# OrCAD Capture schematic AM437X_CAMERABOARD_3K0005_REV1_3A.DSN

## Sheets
1 Pg02: Camera: size C; title: AM437x Camera Board; rev: 1.3A; company: Texas Instruments; note: am437x_cameraboard_3k0005_rev1_3a.dsn; note: ARM MPU BU; note: Final
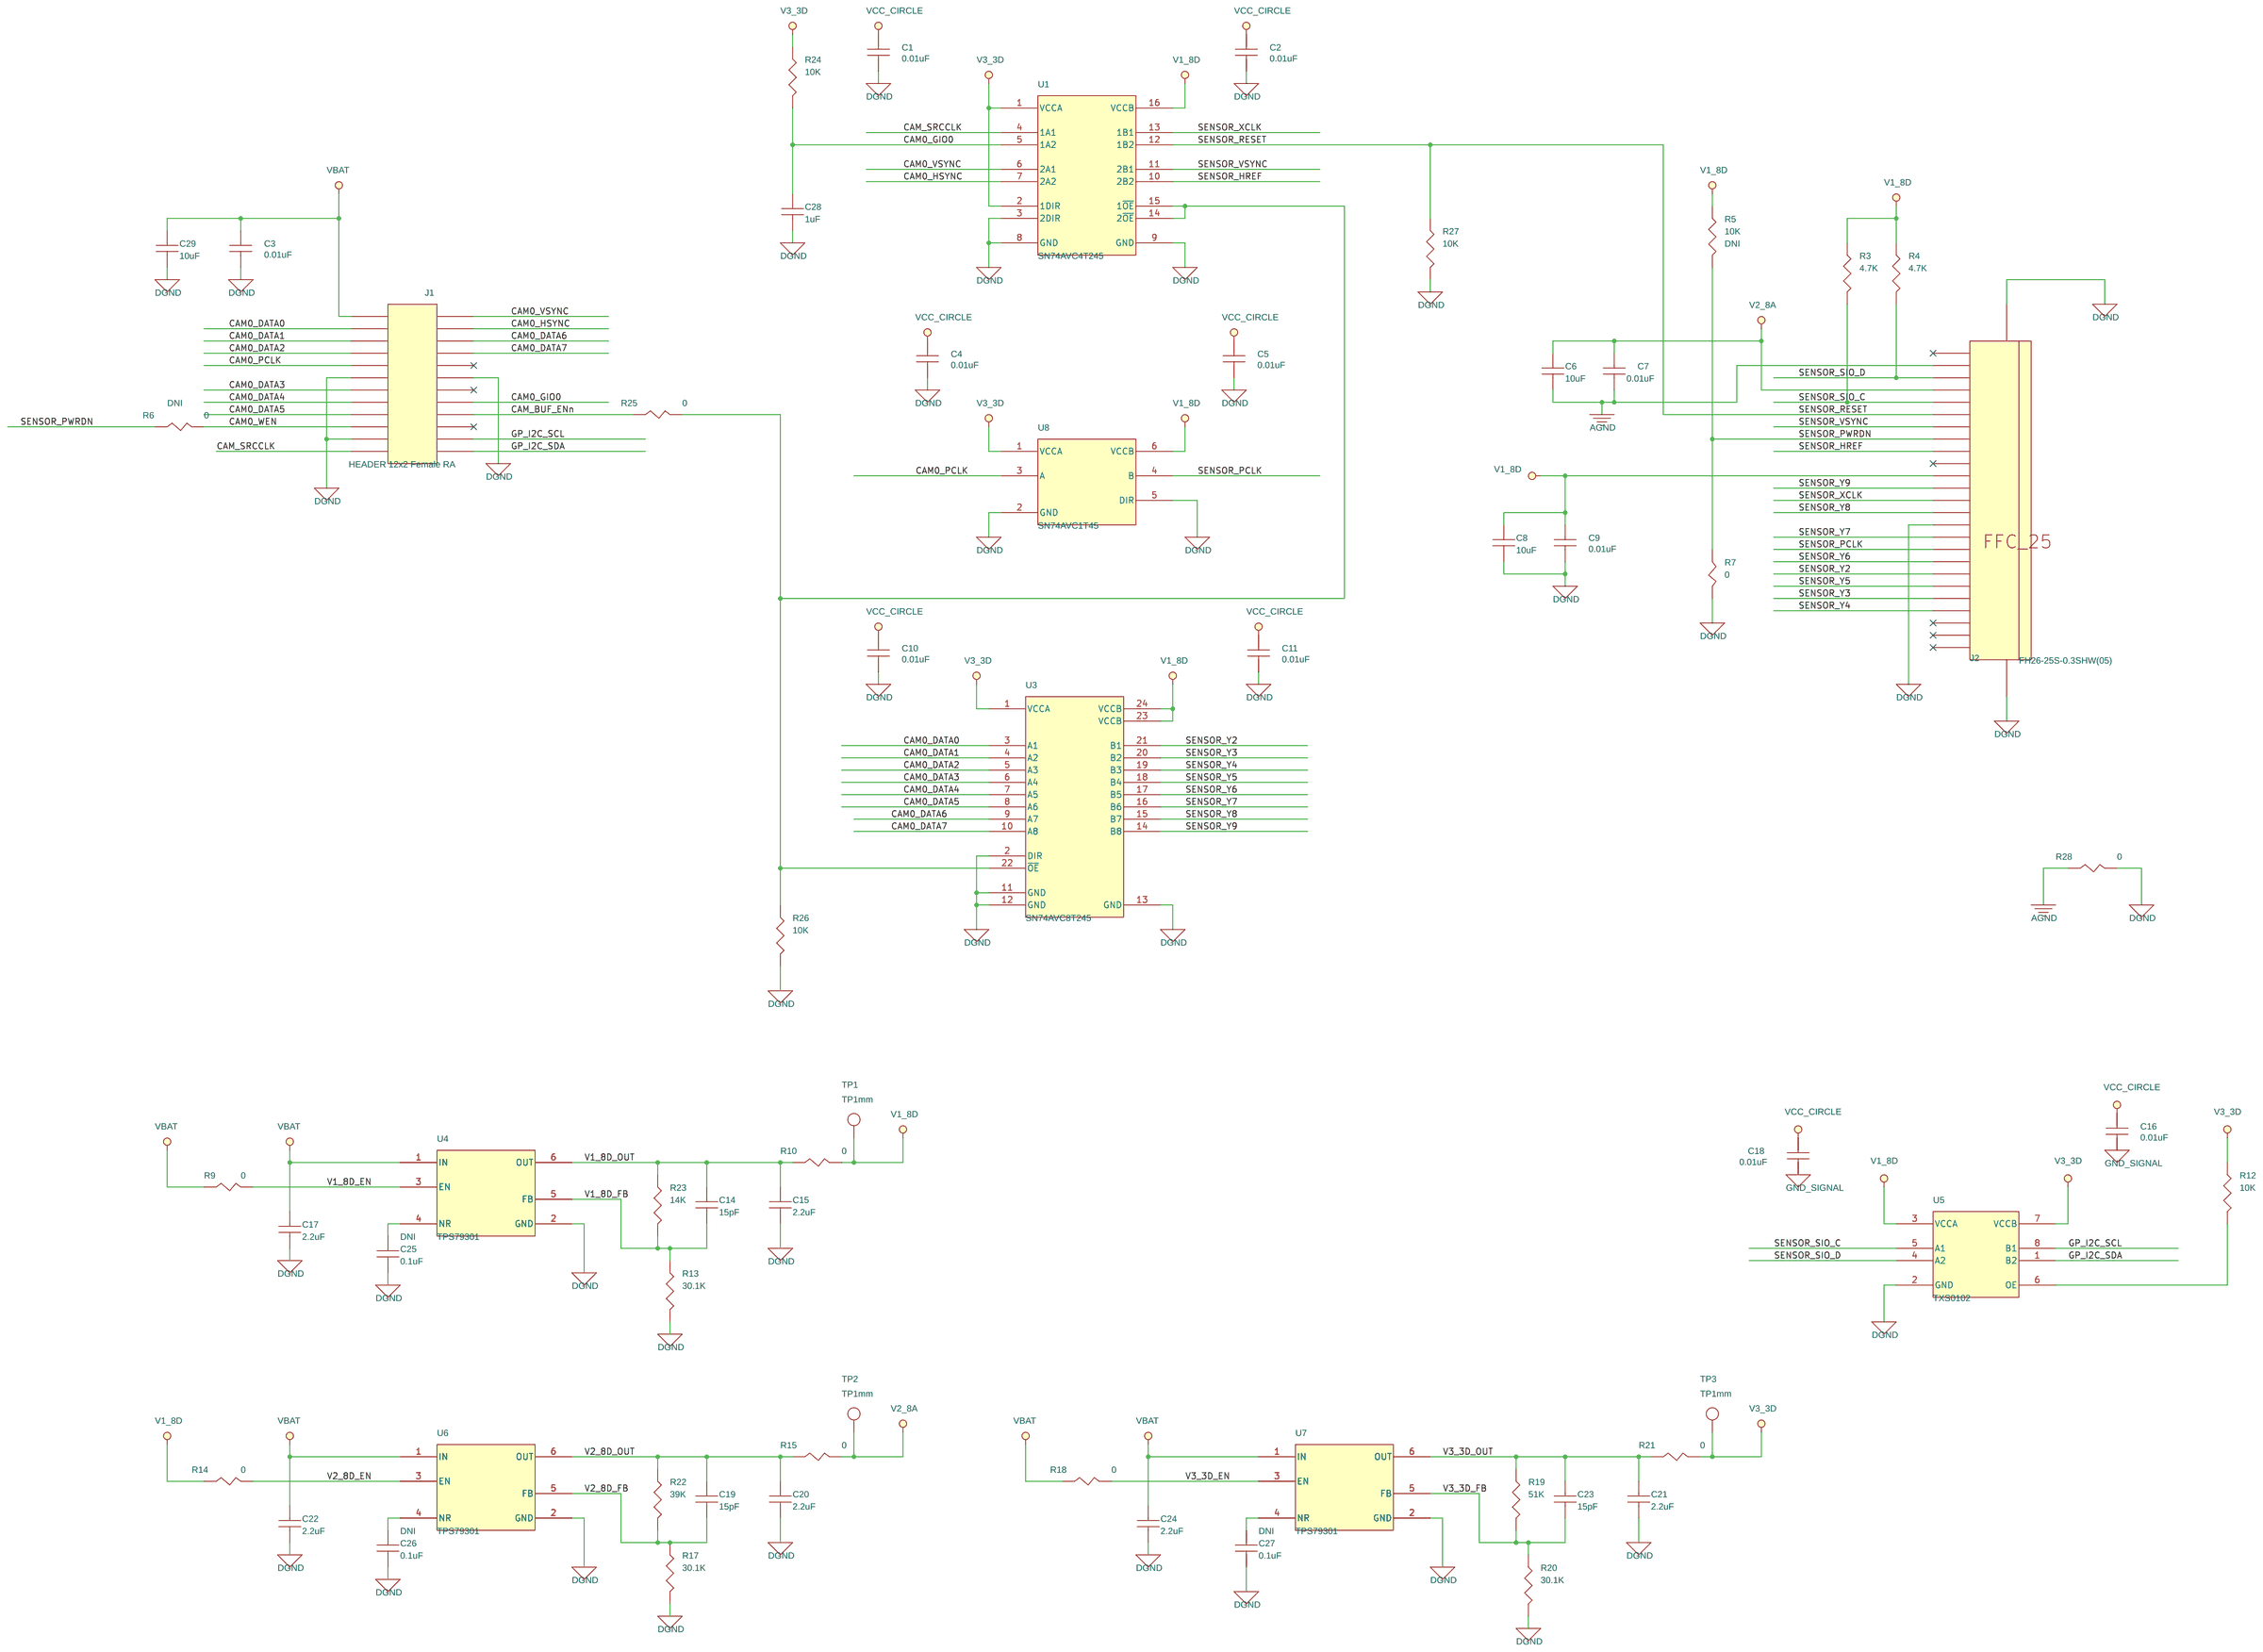
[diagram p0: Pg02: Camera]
2 Pg01: Title
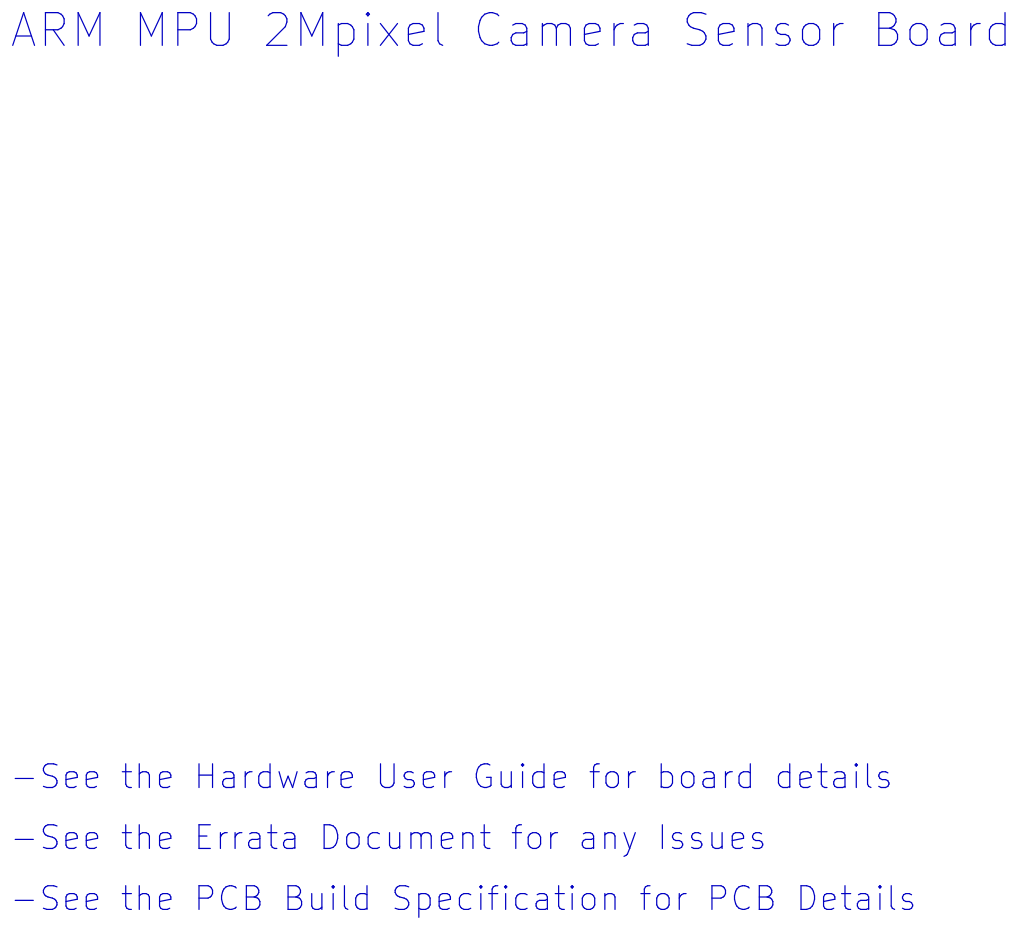
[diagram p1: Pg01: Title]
3 Pg03: Hardware Schematics
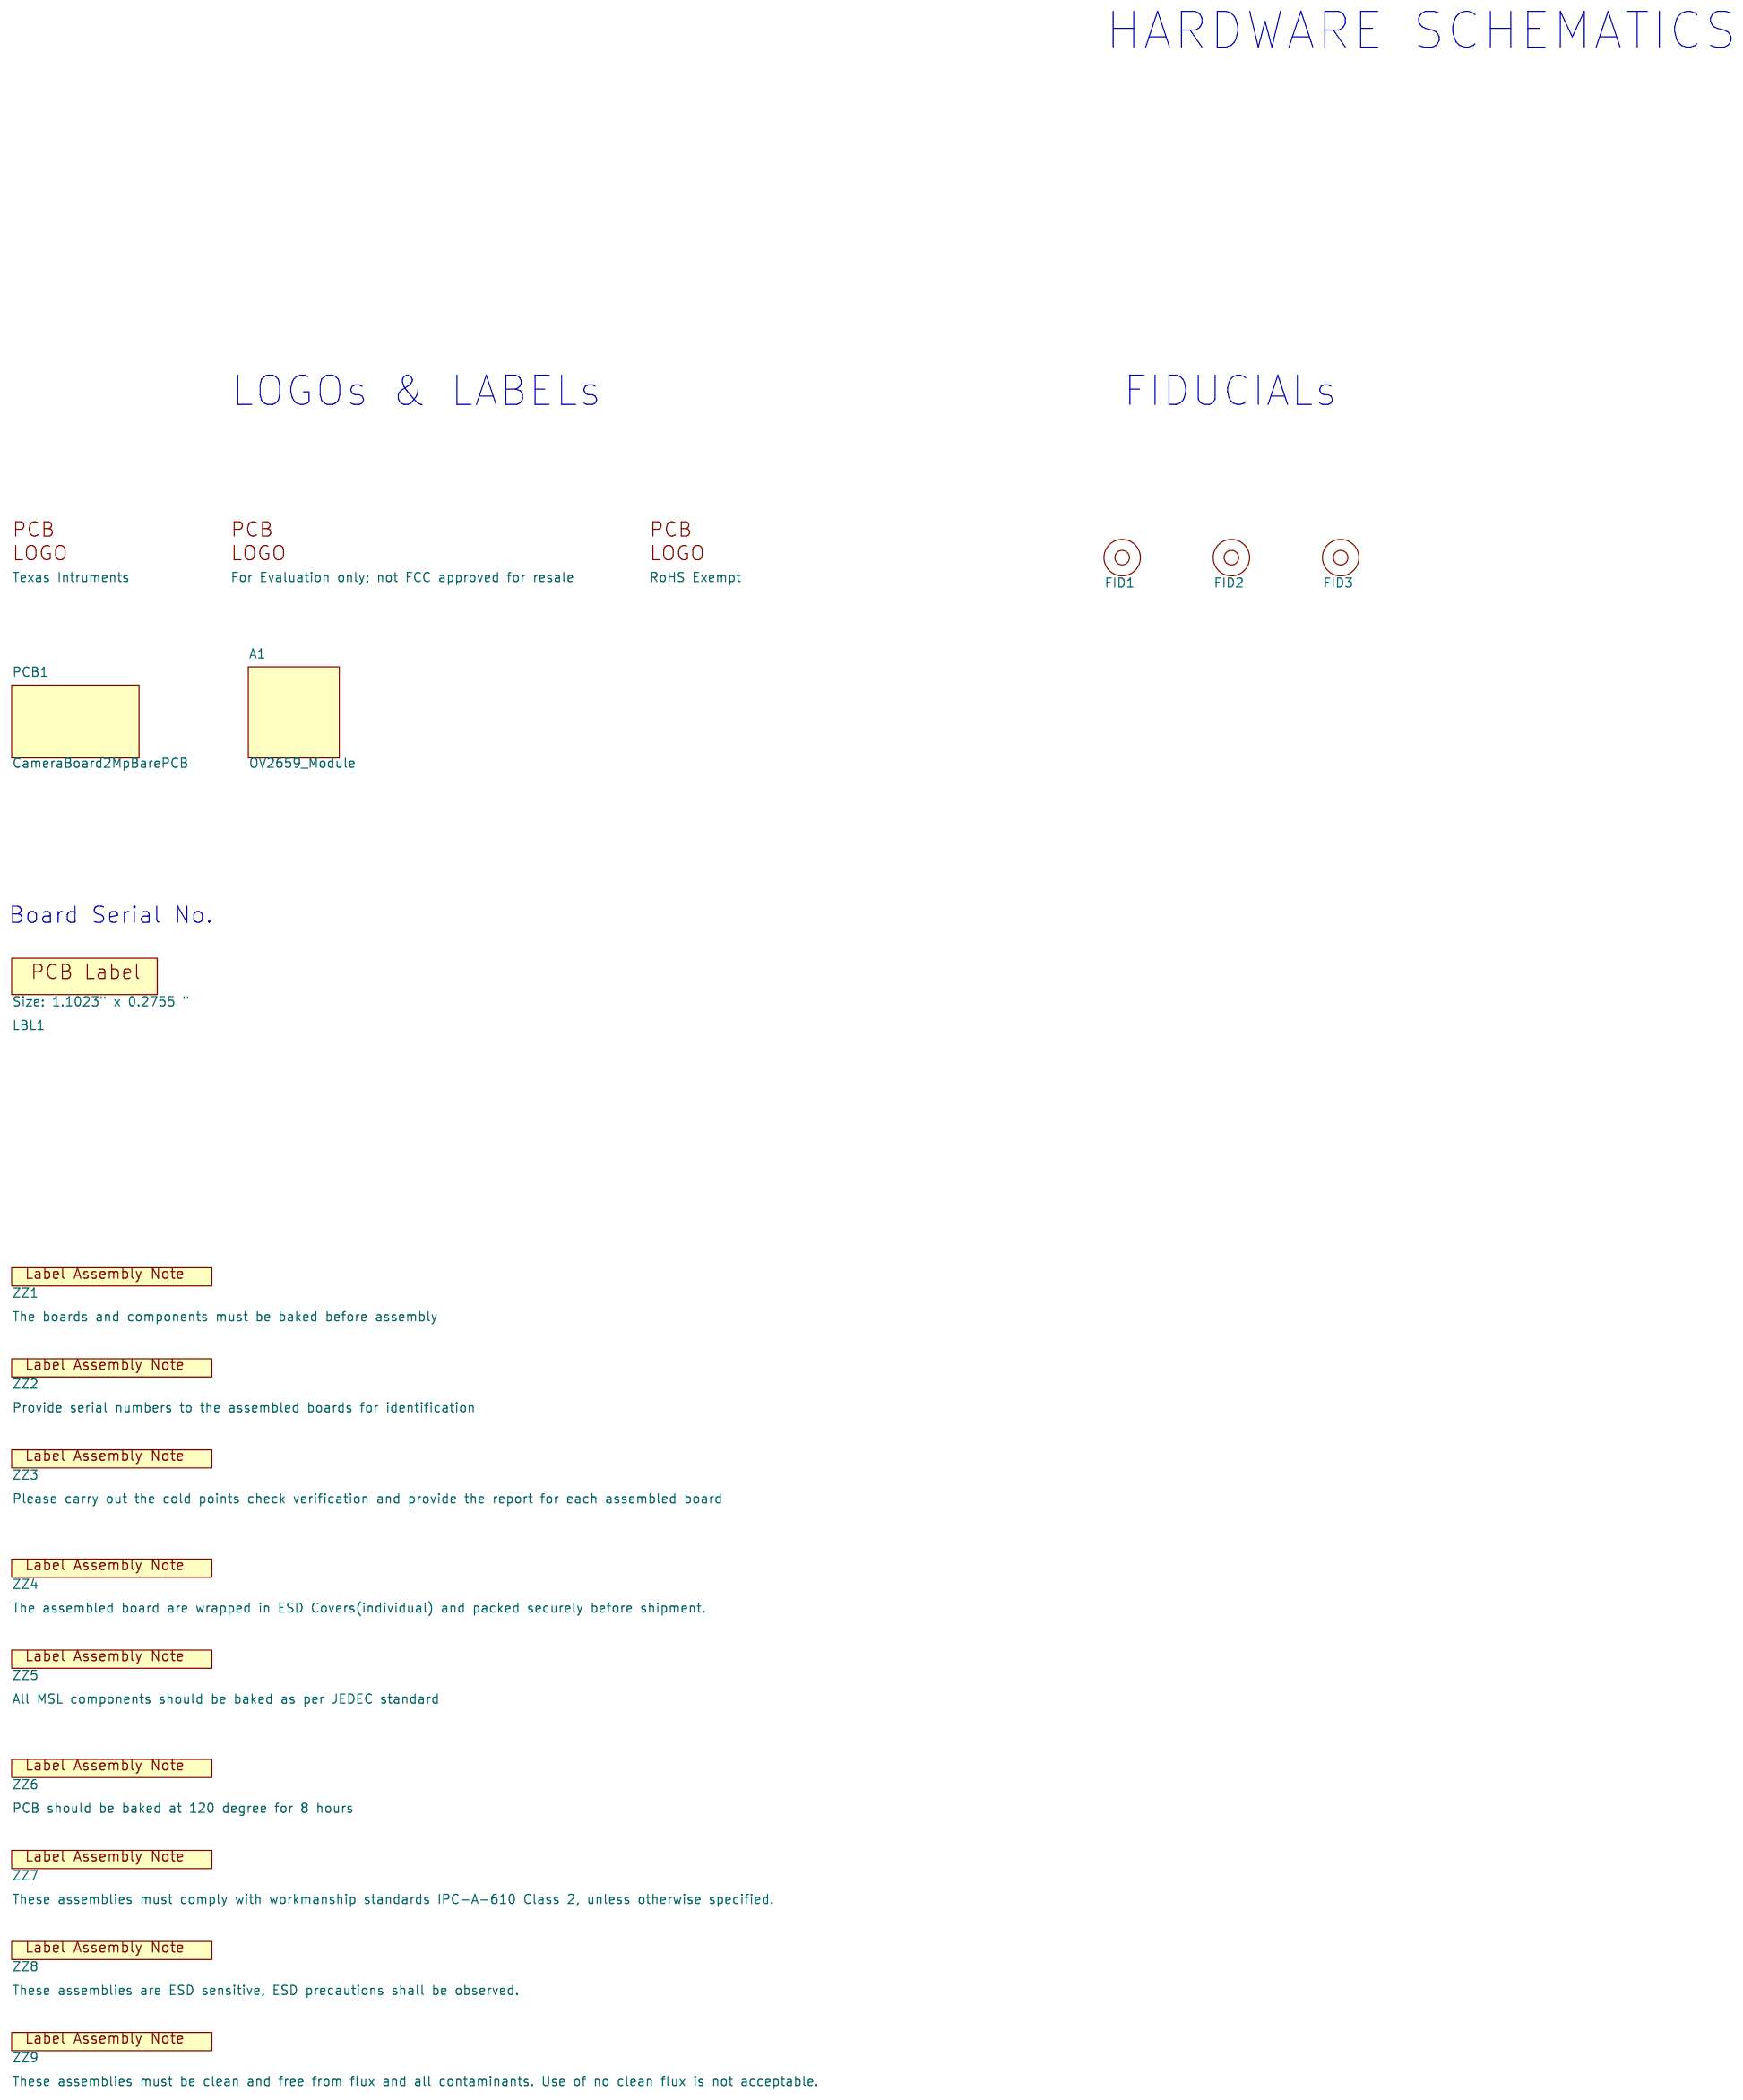
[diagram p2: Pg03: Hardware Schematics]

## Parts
sheet Pg02: Camera
C1  0.01uF  [SM-7351-CAP-0402]
C2  0.01uF  [SM-7351-CAP-0402]
C3  0.01uF  [SM-7351-CAP-0402]
C4  0.01uF  [SM-7351-CAP-0402]
C5  0.01uF  [SM-7351-CAP-0402]
C6  10uF  [SM-7351-CAP-0805]
C7  0.01uF  [SM-7351-CAP-0402]
C8  10uF  [SM-7351-CAP-0805]
C9  0.01uF  [SM-7351-CAP-0402]
C10  0.01uF  [SM-7351-CAP-0402]
C11  0.01uF  [SM-7351-CAP-0402]
C14  15pF  [SM-7351-CAP-0402]
C15  2.2uF  [SM-7351-CAP-0603]
C16  0.01uF  [SM-7351-CAP-0402]
C17  2.2uF  [SM-7351-CAP-0603]
C18  0.01uF  [SM-7351-CAP-0402]
C19  15pF  [SM-7351-CAP-0402]
C20  2.2uF  [SM-7351-CAP-0603]
C21  2.2uF  [SM-7351-CAP-0603]
C22  2.2uF  [SM-7351-CAP-0603]
C23  15pF  [SM-7351-CAP-0402]
C24  2.2uF  [SM-7351-CAP-0603]
C25  0.1uF  [SM-7351-CAP-0402]
C26  0.1uF  [SM-7351-CAP-0402]
C27  0.1uF  [SM-7351-CAP-0402]
C28  1uF  [SM-7351-CAP-0402]
C29  10uF  [SM-7351-CAP-0805]
J1  HEADER 12x2 Female RA  [HDR12X2-205M]
J2  FH26-25S-0.3SHW(05)  [CNFH26-25S]
R3  4.7K  [SM-7351-RES-0402]
R4  4.7K  [SM-7351-RES-0402]
R5  10K  [SM-7351-RES-0402]
R6  0  [SM-7351-RES-0603]
R7  0  [SM-7351-RES-0402]
R9  0  [SM-7351-RES-0402]
R10  0  [SM-7351-RES-0603]
R12  10K  [SM-7351-RES-0402]
R13  30.1K  [SM-7351-RES-0402]
R14  0  [SM-7351-RES-0402]
R15  0  [SM-7351-RES-0603]
R17  30.1K  [SM-7351-RES-0402]
R18  0  [SM-7351-RES-0402]
R19  51K  [SM-7351-RES-0402]
R20  30.1K  [SM-7351-RES-0402]
R21  0  [SM-7351-RES-0603]
R22  39K  [SM-7351-RES-0402]
R23  14K  [SM-7351-RES-0402]
R24  10K  [SM-7351-RES-0402]
R25  0  [SM-7351-RES-0402]
R26  10K  [SM-7351-RES-0402]
R27  10K  [SM-7351-RES-0402]
R28  0  [SM-7351-RES-0402]
TP1  TP1mm  [tp_smd1mmcircle]
TP2  TP1mm  [tp_smd1mmcircle]
TP3  TP1mm  [tp_smd1mmcircle]
U1  SN74AVC4T245  [U_16_PW]
U3  SN74AVC8T245  [TSSOP8x4-24-47m]
U4  TPS79301  [U_6_DBV]
U5  TXS0102  [dct8]
U6  TPS79301  [U_6_DBV]
U7  TPS79301  [U_6_DBV]
U8  SN74AVC1T45  [smdsc70-6]
sheet Pg03: Hardware Schematics
A1  OV2659_Module  [DNP]
FID1  Fiducial  [Fiducial10-20]
FID2  Fiducial  [Fiducial10-20]
FID3  Fiducial  [Fiducial10-20]
LBL1  Size: 1.1023" x 0.2755 "  [Label_650x200]
LOGO1  Texas Intruments  [TI_Stacked_Overlay_Small]
LOGO3  RoHS Exempt  [TI_Stacked_Overlay_Small]
LOGO4  For Evaluation only; not FCC approved for resale  [FCC_disclaimer]
PCB1  CameraBoard2MpBarePCB  [DNP]
ZZ1  The boards and components must be baked before assembly  [AssemblyNoteLabel]
ZZ2  Provide serial numbers to the assembled boards for identification  [AssemblyNoteLabel]
ZZ3  Please carry out the cold points check verification and provide the report for each assembled board  [AssemblyNoteLabel]
ZZ4  The assembled board are wrapped in ESD Covers(individual) and packed securely before shipment.  [AssemblyNoteLabel]
ZZ5  All MSL components should be baked as per JEDEC standard  [AssemblyNoteLabel]
ZZ6  PCB should be baked at 120 degree for 8 hours  [AssemblyNoteLabel]
ZZ7  These assemblies must comply with workmanship standards IPC-A-610 Class 2, unless otherwise specified.  [AssemblyNoteLabel]
ZZ8  These assemblies are ESD sensitive, ESD precautions shall be observed.  [AssemblyNoteLabel]
ZZ9  These assemblies must be clean and free from flux and all contaminants. Use of no clean flux is not acceptable.  [AssemblyNoteLabel]

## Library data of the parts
C1-C5 C7 C9-C11 C16 C18 = 1C_0.01uFCapacitor16V10%0402
C6 C8 C29 = 1C_10uFCapacitor16V10%0805
C14 C19 C23 = 1C_15pFCapacitor50V10%smd0402
C15 C17 C20-C22 C24 = 1C_2.2uFCapacitor6.3V10%smd0603
C25-C27 = 1C_0.1uFCapacitor16V10%0402: Loading: DNI
C28 = 1C_1uFCapacitor10V10%0402
J1 = 2H_HEADER12x2PinFemale_RA
J2 = 2C_Conn_FFC_0.3mm_25pos
R3 R4 = 1R_4.7KOhmResistor1_16W0402
R5 = 1R_10KOhmResistor1_16W0402: Loading: DNI
R6 = 1R_ZeroOhmResistor1_16W0603: Loading: DNI
R7 R9 R14 R18 R25 R28 = 1R_ZeroOhmResistor1_16W0402
R10 R15 R21 = 1R_ZeroOhmResistor1_16W0603
R12 R24 R26 R27 = 1R_10KOhmResistor1_16W0402
R13 R17 R20 = 1R_30.1Kohm1_16W1%smd0402
R19 = 1R_51Kohm1_16W1%smd0402
R22 = 1R_39Kohm1_16W5%smd0402
R23 = 1R_14KOhmResistor1_16W0402
TP1-TP3 = 2H_Testpoint_SMD1mmCircle
U1 = 1A_SN74AVC4T245
U3 = 1A_SN74AVC8T245
U4 U6 U7 = 1A_TPS79301
U5 = 1A_TXS0102
U8 = 1A_SN74AVC1T45
A1 = 4P_CameraModuleOV2659_2MpDI
FID1-FID3 = Fiducial
LBL1 = THT-14-423-10: Serail Number Label
LOGO1 LOGO3 = TI_Logo
LOGO4 = FCC_disclaimer
PCB1 = 3K_2MpCameraBoardBarePCBv1_3: Mistral Part No: NSPN00010
ZZ1-ZZ9 = AssemblyNoteLabel_0

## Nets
AGND: C6.2 C7.2 J2.24 R28.2(P2)
DGND: C1.2 C2.2 C3.2 C4.2 C5.2 C8.2 C9.2 C10.2 C11.2 C15.2 C16.2 C17.2 C18.2 C20.2 C21.2 C22.2 C24.2 C25.2 C26.2 C27.2 C28.2 C29.2 J1.11 J1.12 J1.22 J2.11 J2.MNT1 J2.MNT2 R7.1(P1) R13.1(P1) R17.1(P1) R20.1(P1) R26.1(P1) R27.1(P1) R28.1(P1) U1.3(2DIR) U1.8(GND) U1.9(GND) U3.2(DIR) U3.11(GND) U3.12(GND) U3.13(GND) U4.2(GND) U5.2(GND) U6.2(GND) U7.2(GND) U8.2(GND) U8.5(DIR)
V1_8D: C2.1 C5.1 C8.1 C9.1 C11.1 C18.1 J2.15 R3.2(P2) R4.2(P2) R5.2(P2) R10.1(P1) R14.2(P2) TP1.1 U1.16(VCCB) U3.23(VCCB) U3.24(VCCB) U5.3(VCCA) U8.6(VCCB)
V1_8D_EN: R9.1(P1) U4.3(EN)
V1_8D_FB: C14.2 R13.2(P2) R23.1(P1) U4.5(FB)
V1_8D_OUT: C14.1 C15.1 R10.2(P2) R23.2(P2) U4.6(OUT)
V2_8A: C6.1 C7.1 J2.22 R15.1(P1) TP2.1
V2_8D_EN: R14.1(P1) U6.3(EN)
V2_8D_FB: C19.2 R17.2(P2) R22.1(P1) U6.5(FB)
V2_8D_OUT: C19.1 C20.1 R15.2(P2) R22.2(P2) U6.6(OUT)
V3_3D: C1.1 C4.1 C10.1 C16.1 R12.2(P2) R21.1(P1) R24.2(P2) TP3.1 U1.1(VCCA) U1.2(1DIR) U3.1(VCCA) U5.7(VCCB) U8.1(VCCA)
V3_3D_EN: R18.1(P1) U7.3(EN)
V3_3D_FB: C23.2 R19.1(P1) R20.2(P2) U7.5(FB)
V3_3D_OUT: C21.1 C23.1 R19.2(P2) R21.2(P2) U7.6(OUT)
VBAT: C3.1 C17.1 C22.1 C24.1 C29.1 J1.2 R9.2(P2) R18.2(P2) U4.1(IN) U6.1(IN) U7.1(IN)
CAM0_DATA0: J1.4 U3.3(A1)
CAM0_DATA1: J1.6 U3.4(A2)
CAM0_DATA2: J1.8 U3.5(A3)
CAM0_DATA3: J1.14 U3.6(A4)
CAM0_DATA4: J1.16 U3.7(A5)
CAM0_DATA5: J1.18 U3.8(A6)
CAM0_DATA6: J1.5 U3.9(A7)
CAM0_DATA7: J1.7 U3.10(A8)
CAM0_GIO0: C28.1 J1.15 R24.1(P1) U1.5(1A2)
CAM0_HSYNC: J1.3 U1.7(2A2)
CAM0_PCLK: J1.10 U8.3(A)
CAM0_VSYNC: J1.1 U1.6(2A1)
CAM0_WEN: J1.20 R6.1(P1)
CAM_BUF_ENn: J1.17 R25.2(P2)
CAM_SRCCLK: J1.24 U1.4(1A1)
GP_I2C_SCL: J1.21 U5.8(B1)
GP_I2C_SDA: J1.23 U5.1(B2)
SENSOR_HREF: J2.17 U1.10(2B2)
SENSOR_PCLK: J2.9 U8.4(B)
SENSOR_PWRDN: J2.18 R5.1(P1) R6.2(P2) R7.2(P2)
SENSOR_RESET: J2.20 R27.2(P2) U1.12(1B2)
SENSOR_SIO_C: J2.21 R3.1(P1) U5.5(A1)
SENSOR_SIO_D: J2.23 R4.1(P1) U5.4(A2)
SENSOR_VSYNC: J2.19 U1.11(2B1)
SENSOR_XCLK: J2.13 U1.13(1B1)
SENSOR_Y2: J2.7 U3.21(B1)
SENSOR_Y3: J2.5 U3.20(B2)
SENSOR_Y4: J2.4 U3.19(B3)
SENSOR_Y5: J2.6 U3.18(B4)
SENSOR_Y6: J2.8 U3.17(B5)
SENSOR_Y7: J2.10 U3.16(B6)
SENSOR_Y8: J2.12 U3.15(B7)
SENSOR_Y9: J2.14 U3.14(B8)
N11948546: C26.1 U6.4(NR)
N11951945: R12.1(P1) U5.6(OE)
N11954374: R25.1(P1) R26.2(P2) U1.14(2~{OE}) U1.15(1~{OE}) U3.22(~{OE})
N11959615: C27.1 U7.4(NR)
N12008170: C25.1 U4.4(NR)

Not connected (* = marked no-connect by the designer): J1 9* 13* 19*; J2 1* 2* 3* 16* 25*

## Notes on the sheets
sheet 2
- ARM MPU 2Mpixel Camera Sensor Board
- -See the Hardware User Guide for board details
- -See the Errata Document for any Issues
- -See the PCB Build Specification for PCB Details
sheet 3
- HARDWARE SCHEMATICS
- LOGOs & LABELs
- FIDUCIALs
- Board Serial No.
